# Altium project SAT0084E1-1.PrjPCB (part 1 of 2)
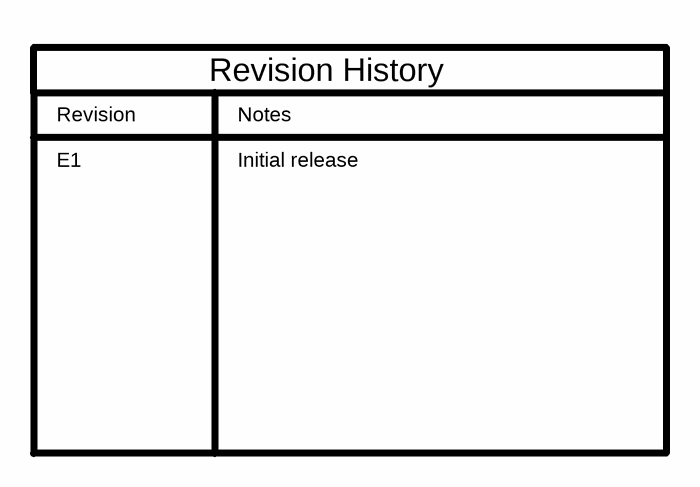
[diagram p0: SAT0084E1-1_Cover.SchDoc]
TechSupport: http://www.ti.com/support; SCH_Rev: E1.1; PRJ_Title: FPD-Link III Class-D Amplifier; PRJ_Number: SAT0084; PRJ_Engineer: Viktor Schneigelberger; PRJ_Customer: Public Release; PCB_Rev: E1.1; PCB_Layout: Krypton Solutions/RS; CopyrightYear: 2014
7 sheets, 381 parts. Net scope: global (net labels, ports and power ports of the same name join across sheets).
Board file: SAT0084E1-1.PcbDoc
Sheets:
  SAT0084E1-1_Cover.SchDoc
  SAT0084E1-1_MCU.SchDoc
  SAT0084E1-1_Power.SchDoc
  SAT0084E1-1_Ser.SchDoc
  SAT0084E1-1_DeSer.SchDoc
  SAT0084E1-1_Backend.SchDoc
  SAT0084E1-1_Hardware.SchDoc

## Sheet SAT0084E1-1_Cover.SchDoc: Cover
size 431 x 279 mm; Date: Not shown in title block; ApprovedBy: Not shown in title block; CheckedBy: Not shown in title block; Author: Not shown in title block; CompanyName: Not shown in title block; DrawnBy: Viktor Schneigelberger; Engineer: Not shown in title block; Organization: Not shown in title block; Address1: Not shown in title block; Address2: Not shown in title block; Address3: Not shown in title block; Address4: Not shown in title block; DocumentNumber: 1; Revision: Use project parameter SCH_Rev; SheetNumber: 1; SheetTotal: 7; PageSetup: Record=PageOptions|CenterHorizontal=True|CenterVertical=True|PrintScale=1.00|XCorrection=1.00|YCorrection=1.00|PrintKind=0|BorderSize=5000000|LeftOffset=0|BottomOffset=0|Orientation=2|PaperLength=1000|PaperWidth=1000|Scale=100|PaperSource=15|PrintQuality=600|MediaType=1|DitherType=10|PaperKind=Letter|PrintScaleMode=1

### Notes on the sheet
- Revision
- Notes
- Revision History
- E1
- Initial release

## Sheet SAT0084E1-1_MCU.SchDoc: MSP430
size 431 x 279 mm; Date: Not shown in title block; ApprovedBy: Not shown in title block; CheckedBy: Not shown in title block; Author: Not shown in title block; CompanyName: Not shown in title block; DrawnBy: Viktor Schneigelberger; Engineer: Not shown in title block; Organization: Not shown in title block; Address1: Not shown in title block; Address2: Not shown in title block; Address3: Not shown in title block; Address4: Not shown in title block; DocumentNumber: 7; Revision: Use project parameter SCH_Rev; SheetNumber: 2; SheetTotal: 7; PageSetup: Record=PageOptions|CenterHorizontal=True|CenterVertical=True|PrintScale=1.00|XCorrection=1.00|YCorrection=1.00|PrintKind=0|BorderSize=5000000|LeftOffset=0|BottomOffset=0|Orientation=2|PaperLength=1000|PaperWidth=1000|Scale=100|PaperSource=15|PrintQuality=600|MediaType=1|DitherType=10|PaperKind=Letter|PrintScaleMode=1
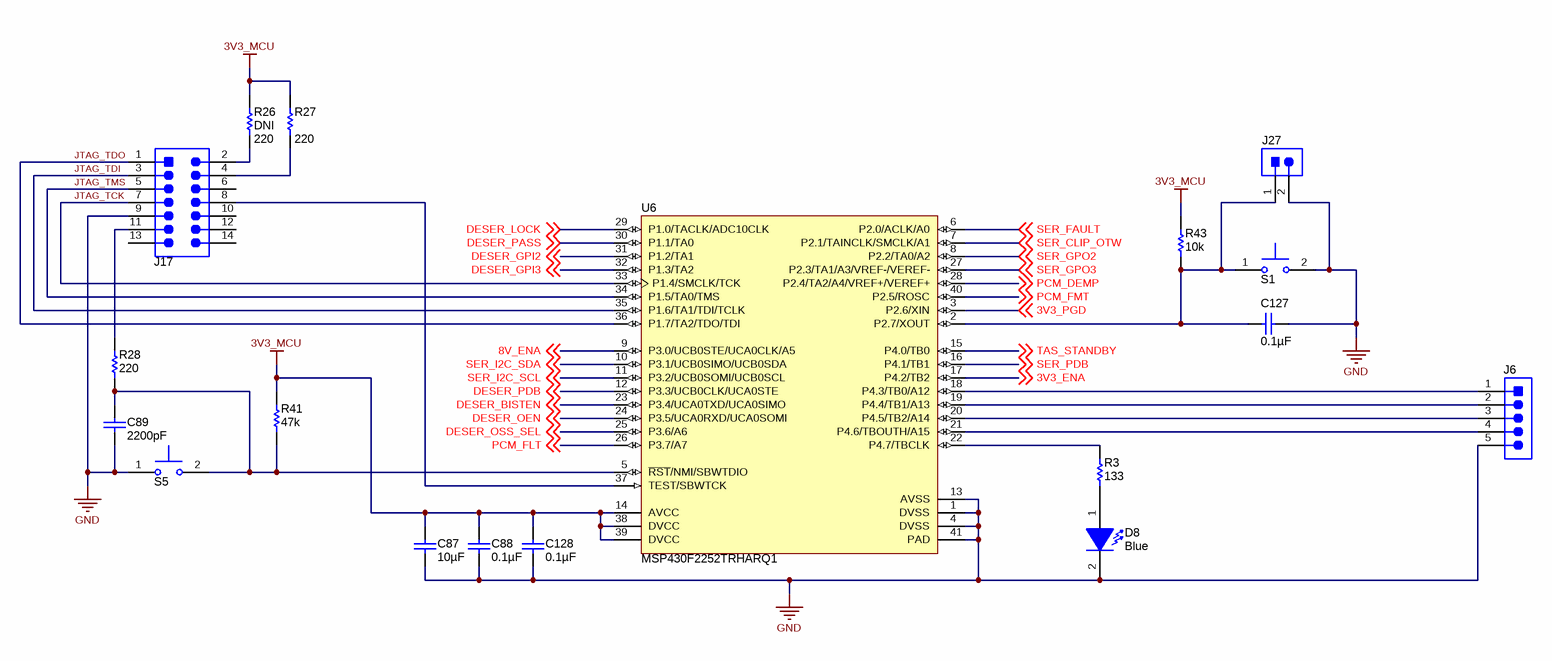
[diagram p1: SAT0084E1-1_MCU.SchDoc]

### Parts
C87  ValueDisplayed: 10µF  [0805_HV]  (hidden comment: GRM21BR71A106KE51L)
C88  ValueDisplayed: 0.1µF  [0402]  (hidden comment: GRM155R71A104KA01D)
C89  ValueDisplayed: 2200pF  [0402]  (hidden comment: GRM155R71C222KA01D)
C127  ValueDisplayed: 0.1µF  [0402]  (hidden comment: GRM155R71A104KA01D)
C128  ValueDisplayed: 0.1µF  [0402]  (hidden comment: GRM155R71A104KA01D)
D8  value Blue  [LED_SMLP12_BLUE]  (hidden comment: SMLP12BC7TT86)
J6  Phase shedding  [TSW-105-07-G-S]  (value not drawn)
J17  JTAG  [CONN_SBH11-PBPC-D07-ST-BK]  (value not drawn)
J27  8V Ena  [TSW-102-07-G-S]  (value not drawn)
R3  value 133  [0402]  (hidden comment: CRCW0402133RFKED)
R26  DNI  value 220  [0402]
R27  220  [0402]
R28  value 220  [0402]  (hidden comment: CRCW0402220RJNED)
R41  value 47k  [0402]  (hidden comment: CRCW040247K0JNED)
R43  value 10k  [0402]  (hidden comment: CRCW040210K0JNED)
S1  S1  [SW_SKRKAEE010]  (value not drawn)
S5  RST  [SW_SKRKAEE010]  (value not drawn)
U6  MSP430F2252TRHARQ1  [RHA0040B]

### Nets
3V3_MCU: C87.1 C88.1 C128.1 R26.1 R27.1 R41.2 R43.2 U6.14(AVCC) U6.38(DVCC) U6.39(DVCC)
GND: C87.2 C88.2 C89.2 C127.2 C128.2 D8.2(K) J6.5 J17.9 J27.2 S1.2 S5.1 U6.1(DVSS) U6.4(DVSS) U6.13(AVSS) U6.41(PAD)
3V3_ENA: U6.17(P4.2/TB2) ; off-sheet 3V3_ENA
3V3_PGD: U6.3(P2.6/XIN) ; off-sheet 3V3_PGD
8V_ENA: U6.9(P3.0/UCB0STE/UCA0CLK/A5) ; off-sheet 8V_ENA
DESER_BISTEN: U6.23(P3.4/UCA0TXD/UCA0SIMO) ; off-sheet DESER_BISTEN
DESER_GPI2: U6.31(P1.2/TA1) ; off-sheet DESER_GPI2
DESER_GPI3: U6.32(P1.3/TA2) ; off-sheet DESER_GPI3
DESER_LOCK: U6.29(P1.0/TACLK/ADC10CLK) ; off-sheet DESER_LOCK
DESER_OEN: U6.24(P3.5/UCA0RXD/UCA0SOMI) ; off-sheet DESER_OEN
DESER_OSS_SEL: U6.25(P3.6/A6) ; off-sheet DESER_OSS_SEL
DESER_PASS: U6.30(P1.1/TA0) ; off-sheet DESER_PASS
DESER_PDB: U6.12(P3.3/UCB0CLK/UCA0STE) ; off-sheet DESER_PDB
JTAG_TCK: J17.7 U6.33(P1.4/SMCLK/TCK)
JTAG_TDI: J17.3 U6.35(P1.6/TA1/TDI/TCLK)
JTAG_TDO: J17.1 U6.36(P1.7/TA2/TDO/TDI)
JTAG_TMS: J17.5 U6.34(P1.5/TA0/TMS)
PCM_DEMP: U6.28(P2.4/TA2/A4/VREF+/VEREF+) ; off-sheet PCM_DEMP
PCM_FLT: U6.26(P3.7/A7) ; off-sheet PCM_FLT
PCM_FMT: U6.40(P2.5/ROSC) ; off-sheet PCM_FMT
SER_CLIP_OTW: U6.7(P2.1/TAINCLK/SMCLK/A1) ; off-sheet SER_CLIP_OTW
SER_FAULT: U6.6(P2.0/ACLK/A0) ; off-sheet SER_FAULT
SER_GPO2: U6.8(P2.2/TA0/A2) ; off-sheet SER_GPO2
SER_GPO3: U6.27(P2.3/TA1/A3/VREF-/VEREF-) ; off-sheet SER_GPO3
SER_I2C_SCL: U6.11(P3.2/UCB0SOMI/UCB0SCL) ; off-sheet SER_I2C_SCL
SER_I2C_SDA: U6.10(P3.1/UCB0SIMO/UCB0SDA) ; off-sheet SER_I2C_SDA
SER_PDB: U6.16(P4.1/TB1) ; off-sheet SER_PDB
TAS_STANDBY: U6.15(P4.0/TB0) ; off-sheet TAS_STANDBY
NetC89_1: C89.1 R28.1 R41.1 S5.2 U6.5(~{RST}/NMI/SBWTDIO)
NetC127_1: C127.1 J27.1 R43.1 S1.1 U6.2(P2.7/XOUT)
NetD8_1: D8.1(A) R3.1
NetJ6_1: J6.1 U6.18(P4.3/TB0/A12)
NetJ6_2: J6.2 U6.19(P4.4/TB1/A13)
NetJ6_3: J6.3 U6.20(P4.5/TB2/A14)
NetJ6_4: J6.4 U6.21(P4.6/TBOUTH/A15)
NetJ17_2: J17.2 R26.2
NetJ17_4: J17.4 R27.2
NetJ17_8: J17.8 U6.37(TEST/SBWTCK)
NetJ17_11: J17.11 R28.2
NetR3_2: R3.2 U6.22(P4.7/TBCLK)

Not connected (* = marked no-connect by the designer): J17 6 10 12 13 14

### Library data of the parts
C87 = GRM21BR71A106KE51L: CAP, CERM, 10uF, 10V, +/-10%, X7R, 0805; Manufacturer: MuRata; Polarized: N; CompType: Capacitor; U/M: EA; Cap_F: 0.00001; Tolerance_%: 10; ESR_Ohm: 0.003; Value1: 0.003 ohm; TaMin_C: -55; TaMax_C: 125; Cap_Case: 0805
C88 C127 C128 = GRM155R71A104KA01D: CAP, CERM, 0.1uF, 10V, +/-10%, X7R, 0402; Manufacturer: MuRata; Polarized: N; CompType: Capacitor; U/M: EA; Cap_F: 0.0000001; Tolerance_%: 10; Value1: Unknown; TaMin_C: -55; TaMax_C: 125
C89 = GRM155R71C222KA01D: CAP, CERM, 2200pF, 16V, +/-10%, X7R, 0402; Manufacturer: MuRata; Polarized: N; CompType: Capacitor; U/M: EA; Cap_F: 0.0000000022; Tolerance_%: 10; Value1: Unknown; VDC_V: 16; TaMin_C: -55; TaMax_C: 125
D8 = SMLP12BC7TT86: LED, Blue, SMD; Manufacturer: Rohm; Type: InGaN; Vf_V: 2.9; Value2: 2.9V; Io_A: 0.005; Tjmax_C: 85; Value1: W; U/M: EA
J6 = TSW-105-07-G-S: Header, TH, 100mil, 5x1, Gold plated, 230 mil above insulator; Manufacturer: Samtec; SymbolCreator: a0412235; U/M: EA
J17 = SBH11-PBPC-D07-ST-BK: Header (shrouded), 100 mil, 7x2, Gold plated, TH; Manufacturer: Sullins Connector Solutions; SymbolCreator: a0412235; CompType: Connector; U/M: EA
J27 = TSW-102-07-G-S: Header, TH, 100mil, 2x1, Gold plated, 230 mil above insulator; Manufacturer: Samtec; SymbolCreator: a0412235; U/M: EA
R3 = CRCW0402133RFKED: RES, 133 ohm, 1%, 0.063W, 0402; Manufacturer: Vishay-Dale; CompType: Resistor; Value_Code: 133R; Tolerance_%: 1; Power_W: 0.063; VDC_V: 50; TempCo: 100 ppm/C; EIA_Code: E96; U/M: EA
R26-R28 = CRCW0402220RJNED: RES, 220 ohm, 5%, 0.063W, 0402; Manufacturer: Vishay-Dale; CompType: Resistor; Value_Code: 220R; Tolerance_%: 5; Power_W: 0.063; VDC_V: 50; TempCo: 200 ppm/C; EIA_Code: E24; U/M: EA
R41 = CRCW040247K0JNED: RES, 47k ohm, 5%, 0.063W, 0402; Manufacturer: Vishay-Dale; CompType: Resistor; Res_ohm: 47000; Value_Code: 47k0; Tolerance_%: 5; Power_W: 0.063; VDC_V: 50; TempCo: 200 ppm/C; EIA_Code: E24; U/M: EA
R43 = CRCW040210K0JNED: RES, 10k ohm, 5%, 0.063W, 0402; Manufacturer: Vishay-Dale; CompType: Resistor; Res_ohm: 10000; Value_Code: 10k0; Tolerance_%: 5; Power_W: 0.063; VDC_V: 50; TempCo: 200 ppm/C; EIA_Code: E24; U/M: EA
S1 S5 = SKRKAEE010: Switch, Push Button, SMD; Manufacturer: Alps; SymbolCreator: a0412235; Circuit: SPST-NO; VDC_V: 12; SwitchFunction: Off-Mom; PositionCount: 1; CurrentRating_mA: 50
U6 = MSP430F2252TRHARQ1: MSP430F22x2  Automotive  Mixed-Signal  Microcontrollers; Manufacturer: Texas Instruments

## Sheet SAT0084E1-1_Power.SchDoc: Power supply
size 431 x 279 mm; Date: Not shown in title block; ApprovedBy: Not shown in title block; CheckedBy: Not shown in title block; Author: Not shown in title block; CompanyName: Not shown in title block; Engineer: Not shown in title block; Organization: Not shown in title block; Address1: Not shown in title block; Address2: Not shown in title block; Address3: Not shown in title block; Address4: Not shown in title block; DocumentNumber: 3; Revision: Use project parameter SCH_Rev; SheetNumber: 3; SheetTotal: 7; PageSetup: Record=PageOptions|CenterHorizontal=True|CenterVertical=True|PrintScale=0.64|XCorrection=1.00|YCorrection=1.00|PrintKind=0|BorderSize=5000000|LeftOffset=0|BottomOffset=0|Orientation=2|PaperLength=1000|PaperWidth=1000|Scale=100|PaperSource=15|PrintQuality=600|MediaType=1|DitherType=10|PaperKind=Letter|PrintScaleMode=1
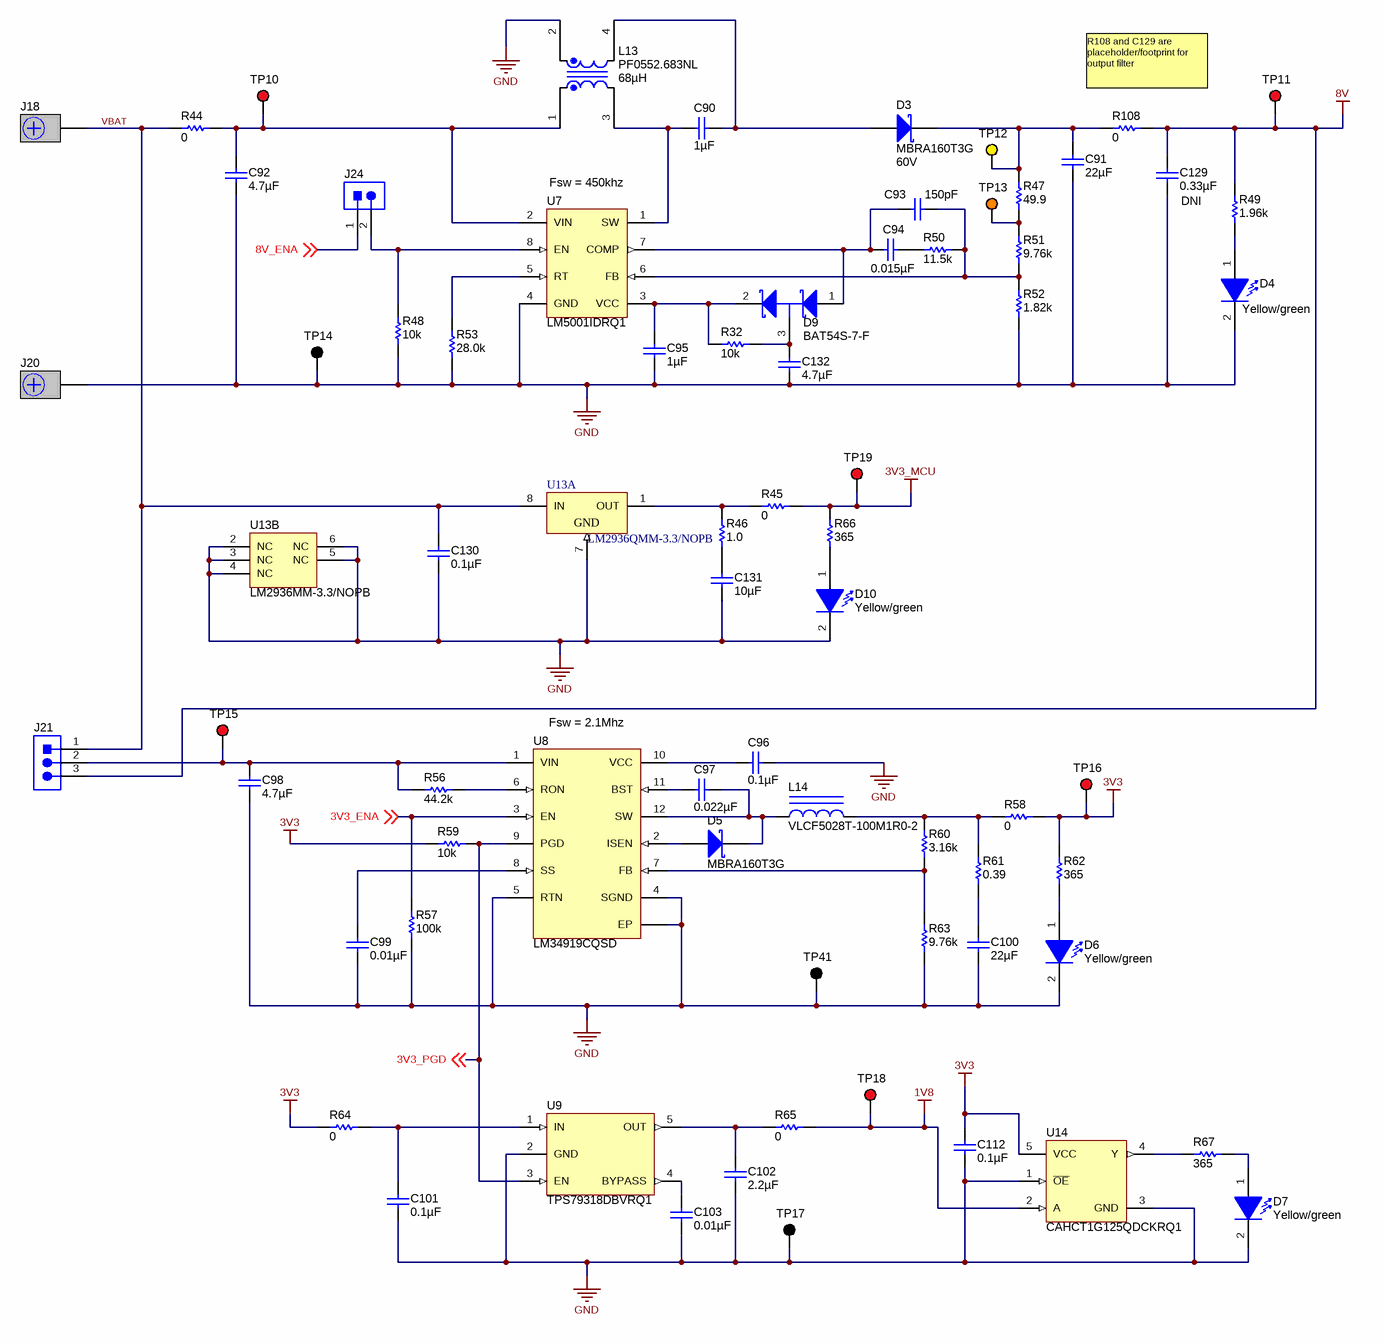
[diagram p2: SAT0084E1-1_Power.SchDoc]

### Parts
C90  ValueDisplayed: 1µF  [1206]  (hidden comment: GRM31CR72A105KA01L)
C91  ValueDisplayed: 22µF  [1206]  (hidden comment: GRM31CR71A226KE15L)
C92  ValueDisplayed: 4.7µF  [1206]  (hidden comment: GRM31CR71H475KA12L)
C93  ValueDisplayed: 150pF  [0603]  (hidden comment: GRM1885C1H151JA01D)
C94  ValueDisplayed: 0.015µF  [0603]  (hidden comment: GRM188R71H153KA01D)
C95  ValueDisplayed: 1µF  [0603]  (hidden comment: C1608X7R1C105K)
C96  ValueDisplayed: 0.1µF  [0402]  (hidden comment: GRM155R71A104KA01D)
C97  ValueDisplayed: 0.022µF  [0402]  (hidden comment: GRM155R71C223KA01D)
C98  ValueDisplayed: 4.7µF  [1206]  (hidden comment: GRM31CR71H475KA12L)
C99  ValueDisplayed: 0.01µF  [0402]  (hidden comment: GRM155R71C103KA01D)
C100  ValueDisplayed: 22µF  [1206]  (hidden comment: GRM31CR71A226KE15L)
C101  ValueDisplayed: 0.1µF  [0402]  (hidden comment: GRM155R71A104KA01D)
C102  ValueDisplayed: 2.2µF  [0603]  (hidden comment: GRM188R71A225KE15D)
C103  ValueDisplayed: 0.01µF  [0402]  (hidden comment: GRM155R71C103KA01D)
C112  ValueDisplayed: 0.1µF  [0402]  (hidden comment: GRM155R71A104KA01D)
C129  DNI  ValueDisplayed: 0.33µF  [0603]
C130  ValueDisplayed: 0.1µF  [0603]  (hidden comment: GCM188R71H104KA57D)
C131  ValueDisplayed: 10µF  [0805_HV]  (hidden comment: GRM21BR71A106KE51L)
C132  ValueDisplayed: 4.7µF  [0805_HV]  (hidden comment: GRM21BR71C475KA73L)
D3  MBRA160T3G  value 60V  [SMA]
D4  value Yellow/green  [SML-P1_YELLOW-GREEN]  (hidden comment: SML-P12MTT86)
D5  MBRA160T3G  [SMA]
D6  value Yellow/green  [SML-P1_YELLOW-GREEN]  (hidden comment: SML-P12MTT86)
D7  value Yellow/green  [SML-P1_YELLOW-GREEN]  (hidden comment: SML-P12MTT86)
D9  BAT54S-7-F  [SOT-23]
D10  value Yellow/green  [SML-P1_YELLOW-GREEN]  (hidden comment: SML-P12MTT86)
J18  VBAT  [CB35-36-CY]  (value not drawn)
J20  GND  [CB35-36-CY]  (value not drawn)
J21  Input Select  [CONN_PEC03SAAN]  (value not drawn)
J24  8V Ena  [TSW-102-07-G-S]  (value not drawn)
L13  PF0552.683NL  ValueDisplayed: 68µH  [PF055X_COUPLED]
L14  VLCF5028T-100M1R0-2  [VLCF5028]
R32  value 10k  [0402]  (hidden comment: CRCW040210K0JNED)
R44  value 0  [0603]  (hidden comment: CRCW06030000Z0EA)
R45  value 0  [0603]  (hidden comment: CRCW06030000Z0EA)
R46  value 1.0  [0603]  (hidden comment: CRCW06031R00JNEA)
R47  value 49.9  [0402]  (hidden comment: CRCW040249R9FKED)
R48  value 10k  [0402]  (hidden comment: CRCW040210K0JNED)
R49  value 1.96k  [0402]  (hidden comment: CRCW04021K96FKED)
R50  value 11.5k  [0603]  (hidden comment: CRCW060311K5FKEA)
R51  value 9.76k  [0402]  (hidden comment: CRCW04029K76FKED)
R52  value 1.82k  [0402]  (hidden comment: CRCW04021K82FKED)
R53  value 28.0k  [0402]  (hidden comment: CRCW040228K0FKED)
R56  value 44.2k  [0402]  (hidden comment: CRCW040244K2FKED)
R57  value 100k  [0402]  (hidden comment: CRCW0402100KJNED)
R58  value 0  [0603]  (hidden comment: CRCW06030000Z0EA)
R59  value 10k  [0402]  (hidden comment: CRCW040210K0JNED)
R60  value 3.16k  [0402]  (hidden comment: CRCW04023K16FKED)
R61  value 0.39  [0402]  (hidden comment: ERJ-2BQFR39X)
R62  value 365  [0402]  (hidden comment: CRCW0402365RFKED)
R63  value 9.76k  [0402]  (hidden comment: CRCW04029K76FKED)
R64  value 0  [0603]  (hidden comment: CRCW06030000Z0EA)
R65  value 0  [0603]  (hidden comment: CRCW06030000Z0EA)
R66  value 365  [0402]  (hidden comment: CRCW0402365RFKED)
R67  value 365  [0402]  (hidden comment: CRCW0402365RFKED)
R108  value 0  [0603]  (hidden comment: CRCW06030000Z0EA)
TP10  VBAT  [Keystone5005]  (value not drawn)
TP11  8V  [Keystone5005]  (value not drawn)
TP12  COMP_P  [Keystone5009]  (value not drawn)
TP13  COMP_M  [Keystone5008]  (value not drawn)
TP14  GND  [Keystone5006]  (value not drawn)
TP15  VIN  [Keystone5005]  (value not drawn)
TP16  3V3  [Keystone5005]  (value not drawn)
TP17  GND  [Keystone5006]  (value not drawn)
TP18  1V8  [Keystone5005]  (value not drawn)
TP19  3V3_MCU  [Keystone5005]  (value not drawn)
TP41  GND  [Keystone5006]  (value not drawn)
U7  LM5001IDRQ1  [D0008A]
U8  LM34919CQSD  [DNT0012B]
U9  TPS79318DBVRQ1  [DBV0005A]
U13  LM2936QMM-3.3/NOPB  [MUA08A_N]  (parts A,B of 2)
U14  CAHCT1G125QDCKRQ1  [DCK0005A]

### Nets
1V8: R65.2 TP18.1 U14.2(A)
3V3: C112.1 R58.2 R59.1 R62.2 R64.1 TP16.1 U14.5(VCC)
3V3_MCU: R45.2 R66.2 TP19.1
8V: C129.1 J21.3 R49.2 R108.2 TP11.1
GND: C91.2 C92.2 C95.2 C96.1 C98.2 C99.2 C100.2 C101.2 C102.2 C103.2 C112.2 C129.2 C130.2 C131.2 C132.2 D4.2(K) D6.2(K) D7.2(K) D10.2(K) J20.1 L13.2 R48.1 R52.1 R53.1 R57.1 R63.1 TP14.1 TP17.1 TP41.1 U7.4(GND) U8.4(SGND) U8.5(RTN) U8.13(EP) U9.2(GND) U13.2(NC) U13.3(NC) U13.4(NC) U13.5(NC) U13.6(NC) U13.7(ADJ) U14.1(~{OE}) U14.3(GND)
3V3_ENA: R57.2 U8.3(EN) ; off-sheet 3V3_ENA
3V3_PGD: R59.2 U8.9(PGD) U9.3(EN) ; off-sheet 3V3_PGD
8V_ENA: J24.1 ; off-sheet 8V_ENA
VBAT: C130.1 J18.1 J21.1 R44.1 U13.8(IN)
NetC90_1: C90.1 D3.2(A) L13.4
NetC90_2: C90.2 L13.3 U7.1(SW)
NetC91_1: C91.1 D3.1(K) R47.2 R108.1 TP12.1
NetC92_1: C92.1 L13.1 R44.2 TP10.1 U7.2(VIN)
NetC93_1: C93.1 R50.2 R51.1 R52.2 U7.6(FB)
NetC93_2: C93.2 C94.2 D9.1(A) U7.7(COMP)
NetC94_1: C94.1 R50.1
NetC95_1: C95.1 D9.2(K) R32.2 U7.3(VCC)
NetC96_2: C96.2 U8.10(VCC)
NetC97_1: C97.1 U8.11(BST)
NetC97_2: C97.2 D5.1(K) L14.1 U8.12(SW)
NetC98_1: C98.1 J21.2 R56.2 TP15.1 U8.1(VIN)
NetC99_1: C99.1 U8.8(SS)
NetC100_1: C100.1 R61.1
NetC101_1: C101.1 R64.2 U9.1(IN)
NetC102_1: C102.1 R65.1 U9.5(OUT)
NetC103_1: C103.1 U9.4(BYPASS)
NetC131_1: C131.1 R46.1
NetC132_1: C132.1 D9.3(C) R32.1
NetD4_1: D4.1(A) R49.1
NetD5_2: D5.2(A) U8.2(ISEN)
NetD6_1: D6.1(A) R62.1
NetD7_1: D7.1(A) R67.1
NetD10_1: D10.1(A) R66.1
NetJ24_2: J24.2 R48.2 U7.8(EN)
NetL14_2: L14.2 R58.1 R60.2 R61.2
NetR45_1: R45.1 R46.2 U13.1(OUT)
NetR47_1: R47.1 R51.2 TP13.1
NetR53_2: R53.2 U7.5(RT)
NetR56_1: R56.1 U8.6(RON)
NetR60_1: R60.1 R63.2 U8.7(FB)
NetR67_2: R67.2 U14.4(Y)

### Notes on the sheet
- (near R108) R108 and C129 are placeholder/footprint for output filter
- (near U7) Fsw = 450khz
- (near U8) Fsw = 2.1Mhz

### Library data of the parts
C90 = GRM31CR72A105KA01L: CAP, CERM, 1uF, 100V, +/-10%, X7R, 1206; Manufacturer: MuRata; Polarized: N; CompType: Capacitor; U/M: EA; Cap_F: 0.000001; Tolerance_%: 10; Value1: Unknown; VDC_V: 100; TaMin_C: -55; TaMax_C: 125; Cap_Case: 2220
C91 C100 = GRM31CR71A226KE15L: CAP, CERM, 22uF, 10V, +/-10%, X7R, 1206; Manufacturer: MuRata; Polarized: N; CompType: Capacitor; U/M: EA; Cap_F: 0.000022; Tolerance_%: 10; Value1: Unknown; TaMin_C: -55; TaMax_C: 125
C92 C98 = GRM31CR71H475KA12L: CAP, CERM, 4.7uF, 50V, +/-10%, X7R, 1206; Manufacturer: MuRata; Polarized: N; CompType: Capacitor; U/M: EA; Cap_F: 0.0000047; Tolerance_%: 10; Value1: Unknown; VDC_V: 50; TaMin_C: -55; TaMax_C: 125; Cap_Case: 2220
C93 = GRM1885C1H151JA01D: CAP, CERM, 150pF, 50V, +/-5%, C0G/NP0, 0603; Manufacturer: MuRata; Polarized: N; CompType: Capacitor; U/M: EA; Cap_F: 0.00000000015; Tolerance_%: 5; Value1: Unknown; VDC_V: 50; TaMin_C: -55; TaMax_C: 125
C94 = GRM188R71H153KA01D: CAP, CERM, 0.015uF, 50V, +/-10%, X7R, 0603; Manufacturer: MuRata; Polarized: N; CompType: Capacitor; U/M: EA; Cap_F: 0.000000015; Tolerance_%: 10; Value1: Unknown; VDC_V: 50; TaMin_C: -55; TaMax_C: 125
C95 = C1608X7R1C105K: CAP, CERM, 1uF, 16V, +/-10%, X7R, 0603; Manufacturer: TDK; Polarized: N; CompType: Capacitor; U/M: EA; Cap_F: 0.000001; Tolerance_%: 10; ESR_Ohm: 0.0057; Value1: 0.0057 ohm; VDC_V: 16; TaMin_C: -55; TaMax_C: 125
C96 C101 C112 = GRM155R71A104KA01D: as C88 on sheet SAT0084E1-1_MCU
C97 = GRM155R71C223KA01D: CAP, CERM, 0.022uF, 16V, +/-10%, X7R, 0402; Manufacturer: MuRata; Polarized: N; CompType: Capacitor; U/M: EA; Cap_F: 0.000000022; Tolerance_%: 10; Value1: Unknown; VDC_V: 16; TaMin_C: -55; TaMax_C: 125
C99 C103 = GRM155R71C103KA01D: CAP, CERM, 0.01uF, 16V, +/-10%, X7R, 0402; Manufacturer: MuRata; Polarized: N; CompType: Capacitor; U/M: EA; Cap_F: 0.00000001; Tolerance_%: 10; Value1: Unknown; VDC_V: 16; TaMin_C: -55; TaMax_C: 125
C102 = GRM188R71A225KE15D: CAP, CERM, 2.2uF, 10V, +/-10%, X7R, 0603; Manufacturer: MuRata; Polarized: N; CompType: Capacitor; U/M: EA; Cap_F: 0.0000022; Tolerance_%: 10; ESR_Ohm: 0.009; Value1: 0.009 ohm; TaMin_C: -55; TaMax_C: 125
C129 = GRM188R71C334KA01D: CAP, CERM, 0.33uF, 16V, +/-10%, X7R, 0603; Manufacturer: MuRata; Polarized: N; CompType: Capacitor; U/M: EA; Cap_F: 0.00000033; Tolerance_%: 10; Value1: Unknown; VDC_V: 16; TaMin_C: -55; TaMax_C: 125
C130 = GCM188R71H104KA57D: CAP, CERM, 0.1uF, 50V, +/-10%, X7R, 0603; Manufacturer: MuRata; Polarized: N; CompType: Capacitor; U/M: EA; Cap_F: 0.0000001; Tolerance_%: 10; ESR_Ohm: 0.02; Value1: 0.02 ohm; VDC_V: 50; IRMS_A: 1.84; TaMin_C: -55; TaMax_C: 125
C131 = GRM21BR71A106KE51L: as C87 on sheet SAT0084E1-1_MCU
C132 = GRM21BR71C475KA73L: CAP, CERM, 4.7uF, 16V, +/-10%, X7R, 0805; Manufacturer: MuRata; Polarized: N; CompType: Capacitor; U/M: EA; Cap_F: 0.0000047; Tolerance_%: 10; ESR_Ohm: 0.006; Value1: 0.006 ohm; VDC_V: 16; TaMin_C: -55; TaMax_C: 125; Cap_Case: 0805
D3 D5 = MBRA160T3G: Diode, Schottky, 60V, 1A, SMA; Manufacturer: ON Semiconductor; U/M: EA; Vf_V: 0.51; Value2: 0.51V; Io_A: 1; Vr_V: 60; TJmax_C: 150; RJC_CperW: 35
D4 D6 D7 D10 = SML-P12MTT86: LED, Yellow/green, SMD; Manufacturer: Rohm; Type: AlInGaP; Vf_V: 2.2; Value2: 2.2V; Io_A: 0.02; Value1: W; U/M: EA
D9 = BAT54S-7-F: Diode, Schottky, 30V, 0.2A, SOT-23; Manufacturer: Diodes Inc.; U/M: EA; Vf_V: 0.65; Value2: 0.65V; Io_A: 0.2; Vr_V: 30; TJmax_C: 125
J18 J20 = CB35-36-CY: Terminal 50A Lug; Manufacturer: Panduit; CompType: Screw Terminal; SymbolCreator: crossc; U/M: EA
J21 = PEC03SAAN: Header, 100mil, 3x1, Tin plated, TH; Manufacturer: Sullins Connector Solutions; SymbolCreator: a0799628; U/M: EA
J24 = TSW-102-07-G-S: as J27 on sheet SAT0084E1-1_MCU
L13 = PF0552.683NL: Coupled inductor, 68uH, 1.35A, 0.2 ohm, +/-20%, SMD; Manufacturer: Pulse Engineering; SymbolCreator: a0412235; Ind_H: 68.0E-6; DCR_ohm: 0.2; Isat: 1.35; Tolerance_%: 20
L14 = VLCF5028T-100M1R0-2: Inductor, Shielded, Ferrite, 10uH, 1.05A, 0.083 ohm, SMD; Manufacturer: TDK; Ind_H: 10.0E-6; ValueDisplayed: 10µH; Imax_A: 1.05; Irms: 2.19A @ 40C rise; Isat: 1.05A @ 30% inductance drop; DCR_ohm: 0.083; U/M: EA
R32 R48 R59 = CRCW040210K0JNED: as R43 on sheet SAT0084E1-1_MCU
R44 R45 R58 R64 R65 R108 = CRCW06030000Z0EA: RES, 0 ohm, 5%, 0.1W, 0603; Manufacturer: Vishay-Dale; CompType: Resistor; Value_Code: 0000; Tolerance_%: 5; Power_W: 0.1; VDC_V: 75; TempCo: 200 ppm/C; EIA_Code: E24; U/M: EA
R46 = CRCW06031R00JNEA: RES, 1.0 ohm, 5%, 0.1W, 0603; Manufacturer: Vishay-Dale; CompType: Resistor; Res_ohm: 1; Value_Code: 1R00; Tolerance_%: 5; Power_W: 0.1; VDC_V: 75; TempCo: 200 ppm/C; EIA_Code: E24; U/M: EA
R47 = CRCW040249R9FKED: RES, 49.9 ohm, 1%, 0.063W, 0402; Manufacturer: Vishay-Dale; CompType: Resistor; Value_Code: 49R9; Tolerance_%: 1; Power_W: 0.063; VDC_V: 50; TempCo: 100 ppm/C; EIA_Code: E96; U/M: EA
R49 = CRCW04021K96FKED: RES, 1.96k ohm, 1%, 0.063W, 0402; Manufacturer: Vishay-Dale; CompType: Resistor; Res_ohm: 1960; Value_Code: 1k96; Tolerance_%: 1; Power_W: 0.063; VDC_V: 50; TempCo: 100 ppm/C; EIA_Code: E96; U/M: EA
R50 = CRCW060311K5FKEA: RES, 11.5k ohm, 1%, 0.1W, 0603; Manufacturer: Vishay-Dale; CompType: Resistor; Res_ohm: 11500; Value_Code: 11k5; Tolerance_%: 1; Power_W: 0.1; VDC_V: 75; TempCo: 100 ppm/C; EIA_Code: E96; U/M: EA
R51 R63 = CRCW04029K76FKED: RES, 9.76k ohm, 1%, 0.063W, 0402; Manufacturer: Vishay-Dale; CompType: Resistor; Res_ohm: 9760; Value_Code: 9k76; Tolerance_%: 1; Power_W: 0.063; VDC_V: 50; TempCo: 100 ppm/C; EIA_Code: E96; U/M: EA
R52 = CRCW04021K82FKED: RES, 1.82k ohm, 1%, 0.063W, 0402; Manufacturer: Vishay-Dale; CompType: Resistor; Res_ohm: 1820; Value_Code: 1k82; Tolerance_%: 1; Power_W: 0.063; VDC_V: 50; TempCo: 100 ppm/C; EIA_Code: E96; U/M: EA
R53 = CRCW040228K0FKED: RES, 28.0k ohm, 1%, 0.063W, 0402; Manufacturer: Vishay-Dale; CompType: Resistor; Res_ohm: 28000; Value_Code: 28k0; Tolerance_%: 1; Power_W: 0.063; VDC_V: 50; TempCo: 100 ppm/C; EIA_Code: E96; U/M: EA
R56 = CRCW040244K2FKED: RES, 44.2k ohm, 1%, 0.063W, 0402; Manufacturer: Vishay-Dale; CompType: Resistor; Res_ohm: 44200; Value_Code: 44k2; Tolerance_%: 1; Power_W: 0.063; VDC_V: 50; TempCo: 100 ppm/C; EIA_Code: E96; U/M: EA
R57 = CRCW0402100KJNED: RES, 100k ohm, 5%, 0.063W, 0402; Manufacturer: Vishay-Dale; CompType: Resistor; Res_ohm: 100000; Tolerance_%: 5; Power_W: 0.063; VDC_V: 50; TempCo: 200 ppm/C; EIA_Code: E24; U/M: EA
R60 = CRCW04023K16FKED: RES, 3.16k ohm, 1%, 0.063W, 0402; Manufacturer: Vishay-Dale; CompType: Resistor; Res_ohm: 3160; Value_Code: 3k16; Tolerance_%: 1; Power_W: 0.063; VDC_V: 50; TempCo: 100 ppm/C; EIA_Code: E96; U/M: EA
R61 = ERJ-2BQFR39X: RES, 0.39 ohm, 1%, 0.125W, 0402; Manufacturer: Panasonic; CompType: Resistor; Value_Code: R390; Tolerance_%: 1; Power_W: 0.125; TempCo: 250 ppm/C; EIA_Code: E96; U/M: EA
R62 R66 R67 = CRCW0402365RFKED: RES, 365 ohm, 1%, 0.063W, 0402; Manufacturer: Vishay-Dale; CompType: Resistor; Value_Code: 365R; Tolerance_%: 1; Power_W: 0.063; VDC_V: 50; TempCo: 100 ppm/C; EIA_Code: E96; U/M: EA
TP10 TP11 TP15 TP16 TP18 TP19 = 5005: Test Point, Compact, Red, TH; Manufacturer: Keystone; CompType: Test Point Loop; U/M: EA
TP12 = 5009: Test Point, Compact, Yellow, TH; Manufacturer: Keystone; CompType: Test Point Loop; U/M: EA
TP13 = 5008: Test Point, Compact, Orange, TH; Manufacturer: Keystone; CompType: Test Point Loop; U/M: EA
TP14 TP17 TP41 = 5006: Test Point, Compact, Black, TH; Manufacturer: Keystone; CompType: Test Point Loop; U/M: EA
U7 = LM5001IDRQ1: LM5001x  High-Voltage  Switch-Mode  Regulator; Manufacturer: Texas Instruments
U8 = LM34919CQSD: LM34919C Ultra Small 42V, 600 mA Constant On-Time Buck Switching Regulator, DNT0012B; Alternate Manufacturer: None; Manufacturer: Texas Instruments; SymbolCreator: a04111947; CompType: IC; U/M: EA
U9 = TPS79318DBVRQ1: LDO Voltage Regulators Ultra Lo Noise Hi PSRR Fast RF 200mA; Manufacturer: Texas Instruments; Input Bias Current - Max: 0.17 mA; Input Voltage MAX: 5.5 V; Number of Outputs: 1 Output; Output Type: Fixed; Output Voltage: 1.8 V; Voltage Regulation Accuracy: 2 %; Input Voltage MIN: + 2.7 V; Line Regulation: 0.05 % / V; Load Regulation: 5 mV; Maximum Power Dissipation: 0.561 W
U13 = LM2936MM-3.3/NOPB: Ultra-Low Quiescent Current LDO Voltage Regulator, 8-pin Mini SOIC, Pb-Free; Manufacturer: Texas Instruments; PackageTopMarking: ZXTT*KBB; PowerWise: N; CompType: LDO IC
U14 = CAHCT1G125QDCKRQ1: IC BUS BUFF GATE 3ST SGL SC70-5; Manufacturer: Texas Instruments; Logic Type: Buffer/Line Driver, Non-Inverting; Number of Elements: 1; Current - Output High, Low: 8mA, 8mA; Voltage - Supply: 3 V ~ 5.5 V

## Sheet SAT0084E1-1_Ser.SchDoc: Serializer
size 431 x 279 mm; Date: Not shown in title block; ApprovedBy: Not shown in title block; CheckedBy: Not shown in title block; Author: Not shown in title block; CompanyName: Not shown in title block; DrawnBy: Viktor Schneigelberger; Engineer: Not shown in title block; Organization: Not shown in title block; Address1: Not shown in title block; Address2: Not shown in title block; Address3: Not shown in title block; Address4: Not shown in title block; DocumentNumber: 4; Revision: Use project parameter SCH_Rev; SheetNumber: 4; SheetTotal: 7; PageSetup: Record=PageOptions|CenterHorizontal=True|CenterVertical=True|PrintScale=1.00|XCorrection=1.00|YCorrection=1.00|PrintKind=0|BorderSize=5000000|LeftOffset=0|BottomOffset=0|Orientation=2|PaperLength=1000|PaperWidth=1000|Scale=100|PaperSource=15|PrintQuality=600|MediaType=1|DitherType=10|PaperKind=Letter|PrintScaleMode=1
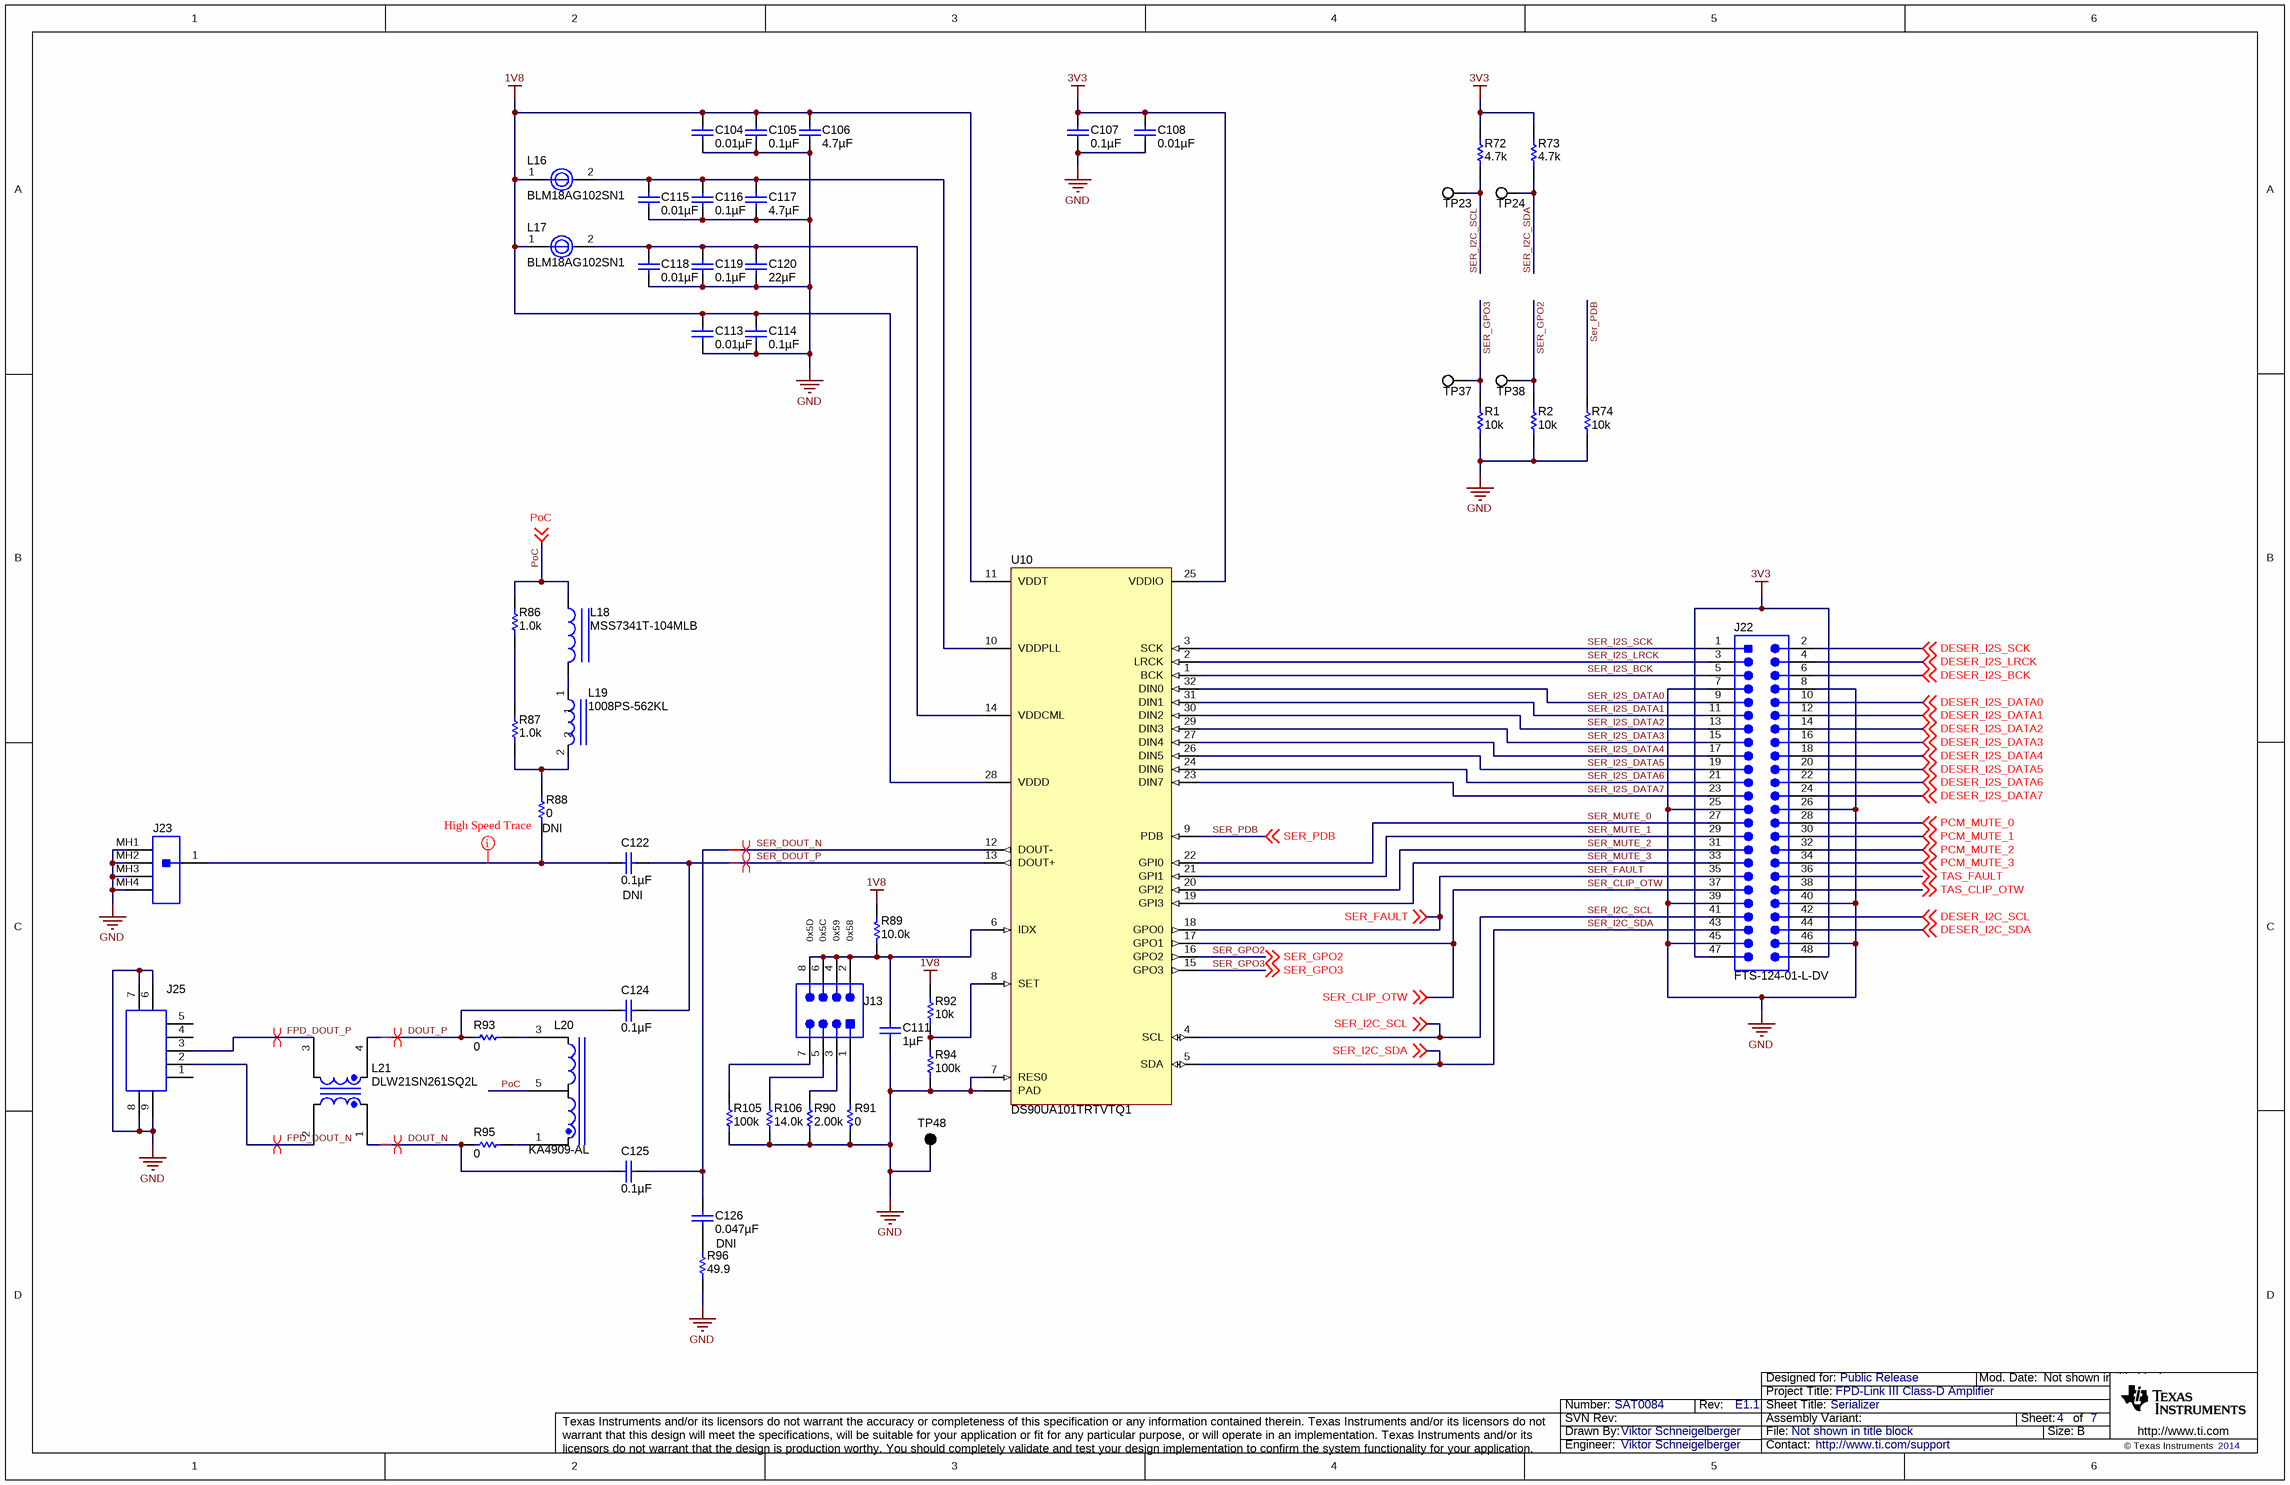
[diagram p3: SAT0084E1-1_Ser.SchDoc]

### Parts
C104  ValueDisplayed: 0.01µF  [0402]  (hidden comment: GRM155R71C103KA01D)
C105  ValueDisplayed: 0.1µF  [0402]  (hidden comment: GRM155R71A104KA01D)
C106  ValueDisplayed: 4.7µF  [0805_HV]  (hidden comment: GRM21BR71C475KA73L)
C107  ValueDisplayed: 0.1µF  [0402]  (hidden comment: GRM155R71A104KA01D)
C108  ValueDisplayed: 0.01µF  [0402]  (hidden comment: GRM155R71C103KA01D)
C111  ValueDisplayed: 1µF  [0603]  (hidden comment: GRM188R71A105KA61D)
C113  ValueDisplayed: 0.01µF  [0402]  (hidden comment: GRM155R71C103KA01D)
C114  ValueDisplayed: 0.1µF  [0402]  (hidden comment: GRM155R71A104KA01D)
C115  ValueDisplayed: 0.01µF  [0402]  (hidden comment: GRM155R71C103KA01D)
C116  ValueDisplayed: 0.1µF  [0402]  (hidden comment: GRM155R71A104KA01D)
C117  ValueDisplayed: 4.7µF  [0805_HV]  (hidden comment: GRM21BR71C475KA73L)
C118  ValueDisplayed: 0.01µF  [0402]  (hidden comment: GRM155R71C103KA01D)
C119  ValueDisplayed: 0.1µF  [0402]  (hidden comment: GRM155R71A104KA01D)
C120  ValueDisplayed: 22µF  [1206]  (hidden comment: GRM31CR71A226KE15L)
C122  DNI  ValueDisplayed: 0.1µF  [0603]
C124  ValueDisplayed: 0.1µF  [0603]  (hidden comment: GRM188R71H104KA93D)
C125  ValueDisplayed: 0.1µF  [0603]  (hidden comment: GRM188R71H104KA93D)
C126  DNI  ValueDisplayed: 0.047µF  [0603]
J13  Addr DeSer  [Samtec_FTS-104-02-x-DV]  (value not drawn)
J22  FTS-124-01-L-DV  [Samtec_FTS-124-01-x-DV]
J23  59S20X-400L5-Y  [Rosenberger_59S20X-400L5]  (value not drawn)
J25  651-305-142-821  [CONN_USB-MINI-AB-651-305-142-821]  (value not drawn)
L16  BLM18AG102SN1  [0603]
L17  BLM18AG102SN1  [0603]
L18  MSS7341T-104MLB  [MSS7341]
L19  1008PS-562KL  [IND_1008PS]
L20  KA4909-AL  [KA4909]
L21  DLW21SN261SQ2L  [IND_DLW21S]
R1  value 10k  [0402]  (hidden comment: CRCW040210K0JNED)
R2  value 10k  [0402]  (hidden comment: CRCW040210K0JNED)
R72  value 4.7k  [0402]  (hidden comment: CRCW04024K70JNED)
R73  value 4.7k  [0402]  (hidden comment: CRCW04024K70JNED)
R74  value 10k  [0402]  (hidden comment: CRCW040210K0JNED)
R86  value 1.0k  [0603]  (hidden comment: CRCW06031K00JNEA)
R87  value 1.0k  [0603]  (hidden comment: CRCW06031K00JNEA)
R88  DNI  value 0  [0603]
R89  value 10.0k  [0402]  (hidden comment: CRCW040210K0FKED)
R90  value 2.00k  [0402]  (hidden comment: CRCW04022K00FKED)
R91  value 0  [0402]  (hidden comment: CRCW04020000Z0ED)
R92  value 10k  [0402]  (hidden comment: CRCW040210K0JNED)
R93  value 0  [0603]  (hidden comment: CRCW06030000Z0EA)
R94  value 100k  [0402]  (hidden comment: CRCW0402100KJNED)
R95  value 0  [0603]  (hidden comment: CRCW06030000Z0EA)
R96  value 49.9  [0402]  (hidden comment: CRCW040249R9FKED)
R105  value 100k  [0402]  (hidden comment: CRCW0402100KFKED)
R106  value 14.0k  [0402]  (hidden comment: CRCW040214K0FKED)
TP23  SCL  [Keystone5007]  (value not drawn)
TP24  SDA  [Keystone5007]  (value not drawn)
TP37  GPO3  [Keystone5007]  (value not drawn)
TP38  GPO2  [Keystone5007]  (value not drawn)
TP48  GND  [Keystone5006]  (value not drawn)
U10  DS90UA101TRTVTQ1  [RTV0032A]

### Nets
1V8: C104.1 C105.1 C106.1 C113.1 C114.1 L16.1 L17.1 R89.2 R92.2 U10.11(VDDT) U10.28(VDDD)
3V3: C107.1 C108.1 J22.47 J22.48 R72.2 R73.2 U10.25(VDDIO)
GND: C104.2 C105.2 C106.2 C107.2 C108.2 C111.2 C113.2 C114.2 C115.2 C116.2 C117.2 C118.2 C119.2 C120.2 J22.7 J22.8 J22.25 J22.26 J22.39 J22.40 J22.45 J22.46 J23.MH1 J23.MH2 J23.MH3 J23.MH4 J25.6 J25.7 J25.8 J25.9 R1.1 R2.1 R74.2 R90.1 R91.1 R94.1 R96.1 R105.1 R106.1 TP48.1 U10.7(RES0) U10.33(PAD)
DESER_I2C_SCL: J22.42 ; off-sheet DESER_I2C_SCL
DESER_I2C_SDA: J22.44 ; off-sheet DESER_I2C_SDA
DESER_I2S_BCK: J22.6 ; off-sheet DESER_I2S_BCK
DESER_I2S_DATA0: J22.10 ; off-sheet DESER_I2S_DATA0
DESER_I2S_DATA1: J22.12 ; off-sheet DESER_I2S_DATA1
DESER_I2S_DATA2: J22.14 ; off-sheet DESER_I2S_DATA2
DESER_I2S_DATA3: J22.16 ; off-sheet DESER_I2S_DATA3
DESER_I2S_DATA4: J22.18 ; off-sheet DESER_I2S_DATA4
DESER_I2S_DATA5: J22.20 ; off-sheet DESER_I2S_DATA5
DESER_I2S_DATA6: J22.22 ; off-sheet DESER_I2S_DATA6
DESER_I2S_DATA7: J22.24 ; off-sheet DESER_I2S_DATA7
DESER_I2S_LRCK: J22.4 ; off-sheet DESER_I2S_LRCK
DESER_I2S_SCK: J22.2 ; off-sheet DESER_I2S_SCK
DOUT_N: C125.2 L21.1 R95.2
DOUT_P: C124.2 L21.4 R93.2
FPD_DOUT_N: J25.2 L21.2
FPD_DOUT_P: J25.3 L21.3
PCM_MUTE_0: J22.28 ; off-sheet PCM_MUTE_0
PCM_MUTE_1: J22.30 ; off-sheet PCM_MUTE_1
PCM_MUTE_2: J22.32 ; off-sheet PCM_MUTE_2
PCM_MUTE_3: J22.34 ; off-sheet PCM_MUTE_3
PoC: L18.1 L20.5 R86.2 ; off-sheet PoC
SER_CLIP_OTW: J22.37 U10.17(GPO1) ; off-sheet SER_CLIP_OTW
SER_DOUT_N: C125.1 C126.1 U10.12(DOUT-)
SER_DOUT_P: C122.1 C124.1 U10.13(DOUT+)
SER_FAULT: J22.35 U10.18(GPO0) ; off-sheet SER_FAULT
SER_GPO2: R2.2 TP38.1 U10.16(GPO2) ; off-sheet SER_GPO2
SER_GPO3: R1.2 TP37.1 U10.15(GPO3) ; off-sheet SER_GPO3
SER_I2C_SCL: J22.41 R72.1 TP23.1 U10.4(SCL) ; off-sheet SER_I2C_SCL
SER_I2C_SDA: J22.43 R73.1 TP24.1 U10.5(SDA) ; off-sheet SER_I2C_SDA
SER_I2S_BCK: J22.5 U10.1(BCK)
SER_I2S_DATA0: J22.9 U10.32(DIN0)
SER_I2S_DATA1: J22.11 U10.31(DIN1)
SER_I2S_DATA2: J22.13 U10.30(DIN2)
SER_I2S_DATA3: J22.15 U10.29(DIN3)
SER_I2S_DATA4: J22.17 U10.27(DIN4)
SER_I2S_DATA5: J22.19 U10.26(DIN5)
SER_I2S_DATA6: J22.21 U10.24(DIN6)
SER_I2S_DATA7: J22.23 U10.23(DIN7)
SER_I2S_LRCK: J22.3 U10.2(LRCK)
SER_I2S_SCK: J22.1 U10.3(SCK)
SER_MUTE_0: J22.27 U10.22(GPI0)
SER_MUTE_1: J22.29 U10.21(GPI1)
SER_MUTE_2: J22.31 U10.20(GPI2)
SER_MUTE_3: J22.33 U10.19(GPI3)
SER_PDB: R74.1 U10.9(PDB) ; off-sheet SER_PDB
TAS_CLIP_OTW: J22.38 ; off-sheet TAS_CLIP_OTW
TAS_FAULT: J22.36 ; off-sheet TAS_FAULT
NetC111_1: C111.1 J13.2 J13.4 J13.6 J13.8 R89.1 U10.6(IDX)
NetC115_1: C115.1 C116.1 C117.1 L16.2 U10.10(VDDPLL)
NetC118_1: C118.1 C119.1 C120.1 L17.2 U10.14(VDDCML)
NetC122_2: C122.2 J23.1 R88.1
NetC126_2: C126.2 R96.2
NetJ13_1: J13.1 R91.2
NetJ13_3: J13.3 R90.2
NetJ13_5: J13.5 R106.2
NetJ13_7: J13.7 R105.2
NetL18_2: L18.2 L19.1
NetL19_2: L19.2 R87.1 R88.2
NetL20_1: L20.1 R95.1
NetL20_3: L20.3 R93.1
NetR86_1: R86.1 R87.2
NetR92_1: R92.1 R94.2 U10.8(SET)

Not connected (* = marked no-connect by the designer): J25 1 4 5

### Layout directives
mark named High Speed Trace: NetC122_2
differential pair: DOUT_N, DOUT_P, FPD_DOUT_N, FPD_DOUT_P, SER_DOUT_N, SER_DOUT_P

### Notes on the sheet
- 0x5D
- 0x5C
- 0x59
- (near R89) 0x58

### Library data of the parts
C104 C108 C113 C115 C118 = GRM155R71C103KA01D: as C99 on sheet SAT0084E1-1_Power
C105 C107 C114 C116 C119 = GRM155R71A104KA01D: as C88 on sheet SAT0084E1-1_MCU
C106 C117 = GRM21BR71C475KA73L: as C132 on sheet SAT0084E1-1_Power
C111 = GRM188R71A105KA61D: CAP, CERM, 1uF, 10V, +/-10%, X7R, 0603; Manufacturer: MuRata; Polarized: N; CompType: Capacitor; U/M: EA; Cap_F: 0.000001; Tolerance_%: 10; ESR_Ohm: 0.011; Value1: 0.011 ohm; TaMin_C: -55; TaMax_C: 125
C120 = GRM31CR71A226KE15L: as C91 on sheet SAT0084E1-1_Power
C122 C124 C125 = GRM188R71H104KA93D: CAP, CERM, 0.1uF, 50V, +/-10%, X7R, 0603; Manufacturer: MuRata; Polarized: N; CompType: Capacitor; U/M: EA; Cap_F: 0.0000001; Tolerance_%: 10; Value1: Unknown; VDC_V: 50; TaMin_C: -55; TaMax_C: 125
C126 = GRM188R71H473KA61D: CAP, CERM, 0.047uF, 50V, +/-10%, X7R, 0603; Manufacturer: MuRata; Polarized: N; CompType: Capacitor; U/M: EA; Cap_F: 0.000000047; Tolerance_%: 10; Value1: Unknown; VDC_V: 50; TaMin_C: -55; TaMax_C: 125
J13 = FTS-104-02-L-DV: Header, 4x2, 1.27mm; Manufacturer: Samtec; SymbolCreator: a0411947; U/M: EA
J22 = FTS-124-01-L-DV: Header, 24x2, 1.27mm; Manufacturer: Samtec; SymbolCreator: x0208326; U/M: EA
J23 = 59S20X-400L5-Y: RIGHT ANGLE PLUG FOR PCB; Manufacturer: Rosenberger; SymbolCreator: x0208325; U/M: EA
J25 = 651-305-142-821: Connector, Receptacle, Mini-USB 2.0, Type AB, R/A, SMT; Manufacturer: Wurth Elektronik eiSos; SymbolCreator: a0799628; U/M: EA
L16 L17 = BEAD-BLM18AG_SERIES: Ferrite Chip, 400 mA, ±25%; Manufacturer: muRata; Area: 5.87 mm; Value: 1k@100MHz
L18 = MSS7341T-104MLB: Inductor, Shielded Drum Core, Ferrite, 100uH, 0.7A, 0.28 ohm, SMD; Manufacturer: Coilcraft; Ind_H: 100.0E-6; ValueDisplayed: 100µH; Imax_A: 0.7; Irms: 1.15A @ 40C rise; Isat: 0.7A @ 30% inductance drop; DCR_ohm: 0.28; U/M: EA
L19 = IND_1008PS-XXXMC: Inductor, 5.6uH, 1.5A, 0.36 ohm, SMD; Manufacturer: Coilcraft; Area: 32400
L20 = KA4909-AL: Inductor, Wirewound, Ferrite, 165uH, 0.65A, 0.46 ohm, SMD; Manufacturer: Coilcraft; SymbolCreator: x0208326; Ind_H: 165.0E-6; ValueDisplayed: 160µH; Imax_A: 0.65; Irms: 0.46A @ 20C rise; DCR_ohm: 0.46; U/M: EA
L21 = DLW21SN900HQ2L: Coupled inductor, 0.3A, 0.4 ohm, +/-25%, SMD; Manufacturer: MuRata; SymbolCreator: a0412235; DCR_ohm: 0.4; Isat: 0.3; Tolerance_%: 25
R1 R2 R74 R92 = CRCW040210K0JNED: as R43 on sheet SAT0084E1-1_MCU
R72 R73 = CRCW04024K70JNED: RES, 4.7k ohm, 5%, 0.063W, 0402; Manufacturer: Vishay-Dale; CompType: Resistor; Res_ohm: 4700; Value_Code: 4k70; Tolerance_%: 5; Power_W: 0.063; VDC_V: 50; TempCo: 200 ppm/C; EIA_Code: E24; U/M: EA
R86 R87 = CRCW06031K00JNEA: RES, 1.0k ohm, 5%, 0.1W, 0603; Manufacturer: Vishay-Dale; CompType: Resistor; Res_ohm: 1000; Value_Code: 1k00; Tolerance_%: 5; Power_W: 0.1; VDC_V: 75; TempCo: 200 ppm/C; EIA_Code: E24; U/M: EA
R88 R93 R95 = CRCW06030000Z0EA: as R44 on sheet SAT0084E1-1_Power
R89 = CRCW040210K0FKED: RES, 10.0k ohm, 1%, 0.063W, 0402; Manufacturer: Vishay-Dale; CompType: Resistor; Res_ohm: 10000; Value_Code: 10k0; Tolerance_%: 1; Power_W: 0.063; VDC_V: 50; TempCo: 100 ppm/C; EIA_Code: E96; U/M: EA
R90 = CRCW04022K00FKED: RES, 2.00k ohm, 1%, 0.063W, 0402; Manufacturer: Vishay-Dale; CompType: Resistor; Res_ohm: 2000; Value_Code: 2k00; Tolerance_%: 1; Power_W: 0.063; VDC_V: 50; TempCo: 100 ppm/C; EIA_Code: E96; U/M: EA
R91 = CRCW04020000Z0ED: RES, 0 ohm, 5%, 0.063W, 0402; Manufacturer: Vishay-Dale; CompType: Resistor; Value_Code: 0000; Tolerance_%: 5; Power_W: 0.063; VDC_V: 50; TempCo: 200 ppm/C; EIA_Code: E24; U/M: EA
R94 = CRCW0402100KJNED: as R57 on sheet SAT0084E1-1_Power
R96 = CRCW040249R9FKED: as R47 on sheet SAT0084E1-1_Power
R105 = CRCW0402100KFKED: RES, 100k ohm, 1%, 0.063W, 0402; Manufacturer: Vishay-Dale; CompType: Resistor; Res_ohm: 100000; Tolerance_%: 1; Power_W: 0.063; VDC_V: 50; TempCo: 100 ppm/C; EIA_Code: E96; U/M: EA
R106 = CRCW040214K0FKED: RES, 14.0k ohm, 1%, 0.063W, 0402; Manufacturer: Vishay-Dale; CompType: Resistor; Res_ohm: 14000; Value_Code: 14k0; Tolerance_%: 1; Power_W: 0.063; VDC_V: 50; TempCo: 100 ppm/C; EIA_Code: E96; U/M: EA
TP23 TP24 TP37 TP38 = 5007: Test Point, Compact, White, TH; Manufacturer: Keystone; CompType: Test Point Loop; U/M: EA
TP48 = 5006: as TP14 on sheet SAT0084E1-1_Power
U10 = DS90UA101TRTVTQ1: Multi-Channel Digital Audio Link, RTV0032A; Alternate Manufacturer: None; Manufacturer: Texas Instruments; SymbolCreator: a0411947; CompType: IC; U/M: EA

## Sheet SAT0084E1-1_DeSer.SchDoc: Deserializer
size 431 x 279 mm; Date: Not shown in title block; ApprovedBy: Not shown in title block; CheckedBy: Not shown in title block; Author: Not shown in title block; CompanyName: Not shown in title block; DrawnBy: Viktor Schneigelberger; Engineer: Not shown in title block; Organization: Not shown in title block; Address1: Not shown in title block; Address2: Not shown in title block; Address3: Not shown in title block; Address4: Not shown in title block; DocumentNumber: 5; Revision: Use project parameter SCH_Rev; SheetNumber: 5; SheetTotal: 7; PageSetup: Record=PageOptions|CenterHorizontal=True|CenterVertical=True|PrintScale=1.00|XCorrection=1.00|YCorrection=1.00|PrintKind=0|BorderSize=5000000|LeftOffset=0|BottomOffset=0|Orientation=2|PaperLength=1000|PaperWidth=1000|Scale=100|PaperSource=15|PrintQuality=600|MediaType=1|DitherType=10|PaperKind=Letter|PrintScaleMode=1
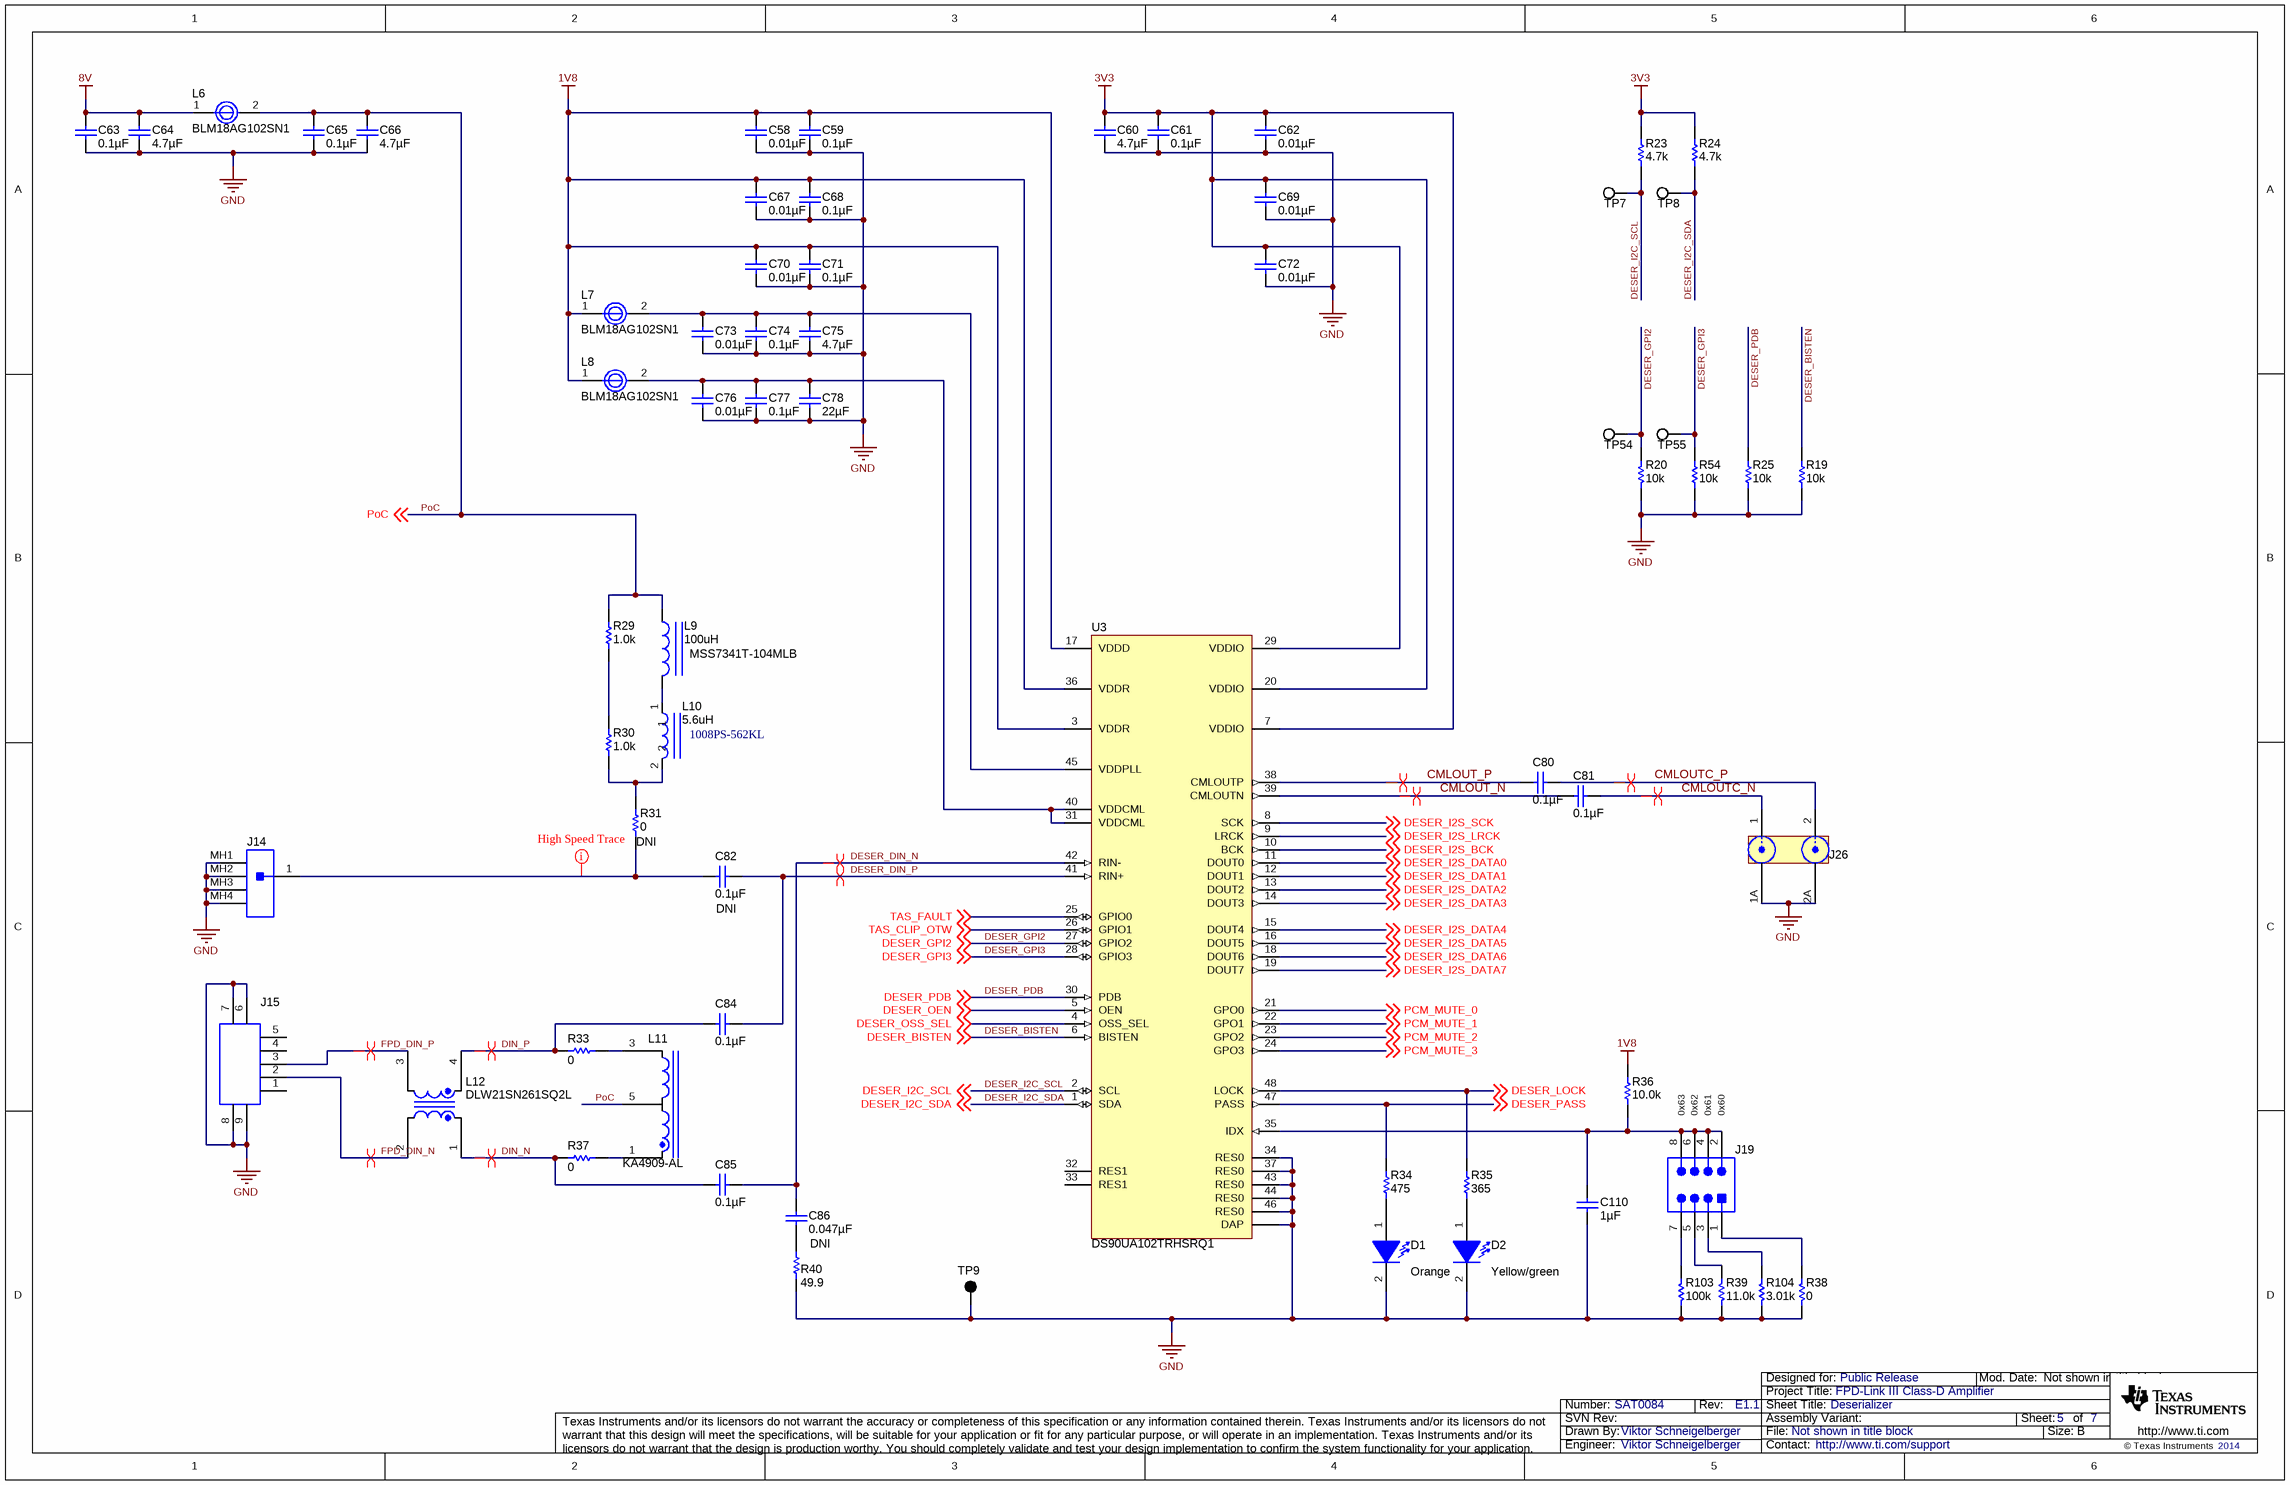
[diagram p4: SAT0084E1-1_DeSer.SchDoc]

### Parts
C58  ValueDisplayed: 0.01µF  [0402]  (hidden comment: GRM155R71C103KA01D)
C59  ValueDisplayed: 0.1µF  [0402]  (hidden comment: GRM155R71A104KA01D)
C60  ValueDisplayed: 4.7µF  [0805_HV]  (hidden comment: GRM21BR71C475KA73L)
C61  ValueDisplayed: 0.1µF  [0402]  (hidden comment: GRM155R71A104KA01D)
C62  ValueDisplayed: 0.01µF  [0402]  (hidden comment: GRM155R71C103KA01D)
C63  ValueDisplayed: 0.1µF  [0402]  (hidden comment: GRM155R71C104KA88D)
C64  ValueDisplayed: 4.7µF  [0805_HV]  (hidden comment: GRM21BR71C475KA73L)
C65  ValueDisplayed: 0.1µF  [0402]  (hidden comment: GRM155R71C104KA88D)
C66  ValueDisplayed: 4.7µF  [0805_HV]  (hidden comment: GRM21BR71C475KA73L)
C67  ValueDisplayed: 0.01µF  [0402]  (hidden comment: GRM155R71C103KA01D)
C68  ValueDisplayed: 0.1µF  [0402]  (hidden comment: GRM155R71A104KA01D)
C69  ValueDisplayed: 0.01µF  [0402]  (hidden comment: GRM155R71C103KA01D)
C70  ValueDisplayed: 0.01µF  [0402]  (hidden comment: GRM155R71C103KA01D)
C71  ValueDisplayed: 0.1µF  [0402]  (hidden comment: GRM155R71A104KA01D)
C72  ValueDisplayed: 0.01µF  [0402]  (hidden comment: GRM155R71C103KA01D)
C73  ValueDisplayed: 0.01µF  [0402]  (hidden comment: GRM155R71C103KA01D)
C74  ValueDisplayed: 0.1µF  [0402]  (hidden comment: GRM155R71A104KA01D)
C75  ValueDisplayed: 4.7µF  [0805_HV]  (hidden comment: GRM21BR71C475KA73L)
C76  ValueDisplayed: 0.01µF  [0402]  (hidden comment: GRM155R71C103KA01D)
C77  ValueDisplayed: 0.1µF  [0402]  (hidden comment: GRM155R71A104KA01D)
C78  ValueDisplayed: 22µF  [1206]  (hidden comment: GRM31CR71A226KE15L)
C80  ValueDisplayed: 0.1µF  [0402]  (hidden comment: C1005X7R1H104K050BB)
C81  ValueDisplayed: 0.1µF  [0402]  (hidden comment: C1005X7R1H104K050BB)
C82  DNI  ValueDisplayed: 0.1µF  [0603]
C84  ValueDisplayed: 0.1µF  [0603]  (hidden comment: GRM188R71H104KA93D)
C85  ValueDisplayed: 0.1µF  [0603]  (hidden comment: GRM188R71H104KA93D)
C86  DNI  ValueDisplayed: 0.047µF  [0603]
C110  ValueDisplayed: 1µF  [0603]  (hidden comment: GRM188R71A105KA61D)
D1  value Orange  [LED_SMLP12_ORANGE]  (hidden comment: SML-P12DTT86)
D2  value Yellow/green  [SML-P1_YELLOW-GREEN]  (hidden comment: SML-P12MTT86)
J14  59S20X-400L5-Y  [Rosenberger_59S20X-400L5]  (value not drawn)
J15  651-305-142-821  [CONN_USB-MINI-AB-651-305-142-821]  (value not drawn)
J19  Addr Ser  [Samtec_FTS-104-02-x-DV]  (value not drawn)
J26  CCH-J-02  [CCH-J-02]  (value not drawn)
L6  BLM18AG102SN1  [0603]
L7  BLM18AG102SN1  [0603]
L8  BLM18AG102SN1  [0603]
L9  100uH  [MSS7341]
L10  5.6uH  PartNumber: 1008PS-562KL  [IND_1008PS]
L11  KA4909-AL  [KA4909]
L12  DLW21SN261SQ2L  [IND_DLW21S]
R19  value 10k  [0402]  (hidden comment: CRCW040210K0JNED)
R20  value 10k  [0402]  (hidden comment: CRCW040210K0JNED)
R23  value 4.7k  [0402]  (hidden comment: CRCW04024K70JNED)
R24  value 4.7k  [0402]  (hidden comment: CRCW04024K70JNED)
R25  value 10k  [0402]  (hidden comment: CRCW040210K0JNED)
R29  value 1.0k  [0603]  (hidden comment: CRCW06031K00JNEA)
R30  value 1.0k  [0603]  (hidden comment: CRCW06031K00JNEA)
R31  DNI  value 0  [0603]
R33  value 0  [0603]  (hidden comment: CRCW06030000Z0EA)
R34  value 475  [0402]  (hidden comment: CRCW0402475RFKED)
R35  value 365  [0402]  (hidden comment: CRCW0402365RFKED)
R36  value 10.0k  [0402]  (hidden comment: CRCW040210K0FKED)
R37  value 0  [0603]  (hidden comment: CRCW06030000Z0EA)
R38  value 0  [0402]  (hidden comment: CRCW04020000Z0ED)
R39  value 11.0k  [0402]  (hidden comment: CRCW040211K0FKED)
R40  value 49.9  [0402]  (hidden comment: CRCW040249R9FKED)
R54  value 10k  [0402]  (hidden comment: CRCW040210K0JNED)
R103  value 100k  [0402]  (hidden comment: CRCW0402100KFKED)
R104  value 3.01k  [0402]  (hidden comment: CRCW04023K01FKED)
TP7  SCL  [Keystone5007]  (value not drawn)
TP8  SDA  [Keystone5007]  (value not drawn)
TP9  GND  [Keystone5006]  (value not drawn)
TP54  GPI2  [Keystone5007]  (value not drawn)
TP55  GPI3  [Keystone5007]  (value not drawn)
U3  DS90UA102TRHSRQ1  [RHS0048A]

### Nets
1V8: C58.1 C59.1 C67.1 C68.1 C70.1 C71.1 L7.1 L8.1 R36.2 U3.3(VDDR) U3.17(VDDD) U3.36(VDDR)
3V3: C60.1 C61.1 C62.1 C69.1 C72.1 R23.2 R24.2 U3.7(VDDIO) U3.20(VDDIO) U3.29(VDDIO)
8V: C63.1 C64.1 L6.1
GND: C58.2 C59.2 C60.2 C61.2 C62.2 C63.2 C64.2 C65.2 C66.2 C67.2 C68.2 C69.2 C70.2 C71.2 C72.2 C73.2 C74.2 C75.2 C76.2 C77.2 C78.2 C110.2 D1.2(K) D2.2(K) J14.MH1 J14.MH2 J14.MH3 J14.MH4 J15.6 J15.7 J15.8 J15.9 J26.1A J26.2A R19.2 R20.2 R25.2 R38.1 R39.1 R40.1 R54.2 R103.1 R104.1 TP9.1 U3.34(RES0) U3.37(RES0) U3.43(RES0) U3.44(RES0) U3.46(RES0) U3.49(DAP)
CMLOUT_N: C81.2 U3.39(CMLOUTN)
CMLOUT_P: C80.1 U3.38(CMLOUTP)
CMLOUTC_N: C81.1 J26.1
CMLOUTC_P: C80.2 J26.2
DESER_BISTEN: R19.1 U3.6(BISTEN) ; off-sheet DESER_BISTEN
DESER_DIN_N: C85.1 C86.1 U3.42(RIN-)
DESER_DIN_P: C82.1 C84.1 U3.41(RIN+)
DESER_GPI2: R20.1 TP54.1 U3.27(GPIO2) ; off-sheet DESER_GPI2
DESER_GPI3: R54.1 TP55.1 U3.28(GPIO3) ; off-sheet DESER_GPI3
DESER_I2C_SCL: R23.1 TP7.1 U3.2(SCL) ; off-sheet DESER_I2C_SCL
DESER_I2C_SDA: R24.1 TP8.1 U3.1(SDA) ; off-sheet DESER_I2C_SDA
DESER_I2S_BCK: U3.10(BCK) ; off-sheet DESER_I2S_BCK
DESER_I2S_DATA0: U3.11(DOUT0) ; off-sheet DESER_I2S_DATA0
DESER_I2S_DATA1: U3.12(DOUT1) ; off-sheet DESER_I2S_DATA1
DESER_I2S_DATA2: U3.13(DOUT2) ; off-sheet DESER_I2S_DATA2
DESER_I2S_DATA3: U3.14(DOUT3) ; off-sheet DESER_I2S_DATA3
DESER_I2S_DATA4: U3.15(DOUT4) ; off-sheet DESER_I2S_DATA4
DESER_I2S_DATA5: U3.16(DOUT5) ; off-sheet DESER_I2S_DATA5
DESER_I2S_DATA6: U3.18(DOUT6) ; off-sheet DESER_I2S_DATA6
DESER_I2S_DATA7: U3.19(DOUT7) ; off-sheet DESER_I2S_DATA7
DESER_I2S_LRCK: U3.9(LRCK) ; off-sheet DESER_I2S_LRCK
DESER_I2S_SCK: U3.8(SCK) ; off-sheet DESER_I2S_SCK
DESER_LOCK: R35.2 U3.48(LOCK) ; off-sheet DESER_LOCK
DESER_OEN: U3.5(OEN) ; off-sheet DESER_OEN
DESER_OSS_SEL: U3.4(OSS_SEL) ; off-sheet DESER_OSS_SEL
DESER_PASS: R34.2 U3.47(PASS) ; off-sheet DESER_PASS
DESER_PDB: R25.1 U3.30(PDB) ; off-sheet DESER_PDB
DIN_N: C85.2 L12.1 R37.2
DIN_P: C84.2 L12.4 R33.2
FPD_DIN_N: J15.2 L12.2
FPD_DIN_P: J15.3 L12.3
PCM_MUTE_0: U3.21(GPO0) ; off-sheet PCM_MUTE_0
PCM_MUTE_1: U3.22(GPO1) ; off-sheet PCM_MUTE_1
PCM_MUTE_2: U3.23(GPO2) ; off-sheet PCM_MUTE_2
PCM_MUTE_3: U3.24(GPO3) ; off-sheet PCM_MUTE_3
PoC: C65.1 C66.1 L6.2 L9.1 L11.5 R29.2 ; off-sheet PoC
TAS_CLIP_OTW: U3.26(GPIO1) ; off-sheet TAS_CLIP_OTW
TAS_FAULT: U3.25(GPIO0) ; off-sheet TAS_FAULT
NetC73_1: C73.1 C74.1 C75.1 L7.2 U3.45(VDDPLL)
NetC76_1: C76.1 C77.1 C78.1 L8.2 U3.31(VDDCML) U3.40(VDDCML)
NetC82_2: C82.2 J14.1 R31.1
NetC86_2: C86.2 R40.2
NetC110_1: C110.1 J19.2 J19.4 J19.6 J19.8 R36.1 U3.35(IDX)
NetD1_1: D1.1(A) R34.1
NetD2_1: D2.1(A) R35.1
NetJ19_1: J19.1 R38.2
NetJ19_3: J19.3 R104.2
NetJ19_5: J19.5 R39.2
NetJ19_7: J19.7 R103.2
NetL9_2: L9.2 L10.1
NetL10_2: L10.2 R30.1 R31.2
NetL11_1: L11.1 R37.1
NetL11_3: L11.3 R33.1
NetR29_1: R29.1 R30.2

Not connected (* = marked no-connect by the designer): J15 1 4 5; U3 32(RES1) 33(RES1)

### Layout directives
mark named High Speed Trace: NetC82_2
differential pair: CMLOUT_N, CMLOUT_P, CMLOUTC_N, CMLOUTC_P, DESER_DIN_N, DESER_DIN_P, DIN_N, DIN_P, FPD_DIN_N, FPD_DIN_P

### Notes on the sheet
- 0x63
- 0x62
- (near J19) 0x61
- (near J19) 0x60

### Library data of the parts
C58 C62 C67 C69 C70 C72 C73 C76 = GRM155R71C103KA01D: as C99 on sheet SAT0084E1-1_Power
C59 C61 C68 C71 C74 C77 = GRM155R71A104KA01D: as C88 on sheet SAT0084E1-1_MCU
C60 C64 C66 C75 = GRM21BR71C475KA73L: as C132 on sheet SAT0084E1-1_Power
C63 C65 = GRM155R71C104KA88D: CAP, CERM, 0.1uF, 16V, +/-10%, X7R, 0402; Manufacturer: MuRata; Polarized: N; CompType: Capacitor; U/M: EA; Cap_F: 0.0000001; Tolerance_%: 10; Value1: Unknown; VDC_V: 16; TaMin_C: -55; TaMax_C: 125
C78 = GRM31CR71A226KE15L: as C91 on sheet SAT0084E1-1_Power
C80 C81 = C1005X7R1H104K050BB: CAP, CERM, 0.1uF, 50V, +/-10%, X7R, 0402; Manufacturer: TDK; Polarized: N; CompType: Capacitor; U/M: EA; Cap_F: 0.0000001; Tolerance_%: 10; Value1: Unknown; VDC_V: 50; TaMin_C: -55; TaMax_C: 125
C82 C84 C85 = GRM188R71H104KA93D: as C122 on sheet SAT0084E1-1_Ser
C86 = GRM188R71H473KA61D: as C126 on sheet SAT0084E1-1_Ser
C110 = GRM188R71A105KA61D: as C111 on sheet SAT0084E1-1_Ser
D1 = SML-P12DTT86: LED, Orange, SMD; Manufacturer: Rohm; Type: InGaN; Vf_V: 2.1; Value2: 2.1V; Io_A: 0.02; Tjmax_C: 85; Value1: W; U/M: EA
D2 = SML-P12MTT86: as D4 on sheet SAT0084E1-1_Power
J14 = 59S20X-400L5-Y: as J23 on sheet SAT0084E1-1_Ser
J15 = 651-305-142-821: as J25 on sheet SAT0084E1-1_Ser
J19 = FTS-104-02-L-DV: as J13 on sheet SAT0084E1-1_Ser
J26 = CCH-J-02: Double Compliant Coax Assembly; Manufacturer: Samtec
L6-L8 = BEAD-BLM18AG_SERIES: as L16 on sheet SAT0084E1-1_Ser
L9 = MSS7341T-104MLB: as L18 on sheet SAT0084E1-1_Ser
L10 = IND_1008PS-XXXMC: as L19 on sheet SAT0084E1-1_Ser
L11 = KA4909-AL: as L20 on sheet SAT0084E1-1_Ser
L12 = DLW21SN900HQ2L: as L21 on sheet SAT0084E1-1_Ser
R19 R20 R25 R54 = CRCW040210K0JNED: as R43 on sheet SAT0084E1-1_MCU
R23 R24 = CRCW04024K70JNED: as R72 on sheet SAT0084E1-1_Ser
R29 R30 = CRCW06031K00JNEA: as R86 on sheet SAT0084E1-1_Ser
R31 R33 R37 = CRCW06030000Z0EA: as R44 on sheet SAT0084E1-1_Power
R34 = CRCW0402475RFKED: RES, 475 ohm, 1%, 0.063W, 0402; Manufacturer: Vishay-Dale; CompType: Resistor; Value_Code: 475R; Tolerance_%: 1; Power_W: 0.063; VDC_V: 50; TempCo: 100 ppm/C; EIA_Code: E96; U/M: EA
R35 = CRCW0402365RFKED: as R62 on sheet SAT0084E1-1_Power
R36 = CRCW040210K0FKED: as R89 on sheet SAT0084E1-1_Ser
R38 = CRCW04020000Z0ED: as R91 on sheet SAT0084E1-1_Ser
R39 = CRCW040211K0FKED: RES, 11.0k ohm, 1%, 0.063W, 0402; Manufacturer: Vishay-Dale; CompType: Resistor; Res_ohm: 11000; Value_Code: 11k0; Tolerance_%: 1; Power_W: 0.063; VDC_V: 50; TempCo: 100 ppm/C; EIA_Code: E96; U/M: EA
R40 = CRCW040249R9FKED: as R47 on sheet SAT0084E1-1_Power
R103 = CRCW0402100KFKED: as R105 on sheet SAT0084E1-1_Ser
R104 = CRCW04023K01FKED: RES, 3.01k ohm, 1%, 0.063W, 0402; Manufacturer: Vishay-Dale; CompType: Resistor; Res_ohm: 3010; Value_Code: 3k01; Tolerance_%: 1; Power_W: 0.063; VDC_V: 50; TempCo: 100 ppm/C; EIA_Code: E96; U/M: EA
TP7 TP8 TP54 TP55 = 5007: as TP23 on sheet SAT0084E1-1_Ser
TP9 = 5006: as TP14 on sheet SAT0084E1-1_Power
U3 = DS90UA102TRHSRQ1: IC SER/DESER 10-50MHZ 8B 48-WQFN; Manufacturer: Texas Instruments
